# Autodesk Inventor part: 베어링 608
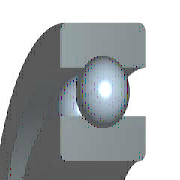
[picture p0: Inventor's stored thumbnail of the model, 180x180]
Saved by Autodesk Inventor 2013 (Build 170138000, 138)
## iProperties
IsCustomPart: 1
Created: 2012-02
Part Number: 베어링 608
Material: 강철, 연강
Description: 깊은 그루브 볼 베어링
Document SubType Name: Modeling
Standard: KS B 2023
Designer: mduedu
Standards Organization: KS
Language: ko-KR
Size Designation: 608 - 8 x 22 x 7
Categories: <MemberInstance><Categories><Category DisplayName="샤프트 부품" InternalName="7f7aeb1f-a693-4053-b835-cee3144e0d98" Mnemonic="SHFT"><Category DisplayName="베어링" Inter
Density: 1 g/cm^3
Author: mduedu
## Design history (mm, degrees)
sketch "스케치" dims "d0" = 3.64 (= -0.26 x WD + 0.26 x BD)
  geometry: L1 (1.68, 7.5)-(5.32, 7.5); L2 (3.5, 7.5)-(3.5, 5.68); L3 (3.5, 7.5)-(3.5, 9.32); L4 (2.148, 6.282)-(0, 6.282); L5 (0, 4)-(7, 4); L6 (2.148, 8.718)-(0, 8.718); L7 (0, 11)-(7, 11); L8 (7, 4)-(7, 6.282); L9 (4.852, 6.282)-(7, 6.282); L10 (4.852, 8.718)-(7, 8.718); L11 (7, 11)-(7, 8.718); L12 (-1.4, 0)-(8.4, 0) reference; L13 (0, -0.3)-(0, 5.3) reference
  constraints: 22 end point, 4 point on line, 2 collinear, 2 perpendicular, 2 symmetric about line, 1 midpoint, 1 parallel, 14 other
  dimensions: "d9" = 8 diameter of L5 L12 (= WD); "d11" = 22 diameter of L7 L12 (= BD); "d12" = 7 distance between parallel lines of L8 L13 (= KB); "d13" = 12.564 diameter of L9 L12 (= 0.326 x BD + 0.674 x WD)
revolve "본체" stored, may be unused: angle "d6" = 90 deg
revolve "볼" stored, may be unused: angle "d7" = 90 deg
pattern_circular "IDS_ARRAYBALL[SIMPL:T]" dims angle "d3" = 360 deg
body "Solid1"
fillet "모깎기1" dims "d1" = 0.3 (= KRS)
other parameters: "WD" = 8 [user parameter; used in 5 equation terms], "BD" = 22 [user parameter; used in 5 equation terms], "KB" = 7 [user parameter; used in 1 equation term], "KRS" = 0.3 [user parameter; used in 1 equation term], "d4" = 0, "d5" = 0, "d8" = 0, "d14" = 0, "d15" = 0, "BBA" = 0 [user parameter], "BC0" = 1370000 [user parameter], "BC" = 3250000 [user parameter], "BR" = 11 (= 0.5 x BD) [user parameter], "WR" = 4 (= 0.5 x WD) [user parameter]
